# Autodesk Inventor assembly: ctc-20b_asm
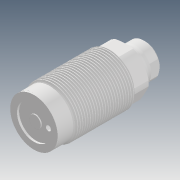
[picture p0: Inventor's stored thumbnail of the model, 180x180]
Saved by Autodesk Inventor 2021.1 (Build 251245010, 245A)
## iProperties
Created: 2018-08
Part Number: ctc-20b_asm
Description: STEP AP203
Document SubType Name: Assembly
Designer: user
Title: ctc-20b_asm.STEP
Revision Number: ÈÎºÎ
Sending System: SolidWorks 2015
Preprocessor: SwSTEP 2.0
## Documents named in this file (6)
- D:\Vault_2016\Projekty\Clamptek\Hydraulic\CTC\Inventor\ctc-20b\ctc-20b_asm.iam
- D:\Vault_2016\Projekty\Clamptek\Hydraulic\CTC\Inventor\ctc-20b\CTC-20BT.ipt
- D:\Vault_2016\Projekty\Clamptek\Hydraulic\CTC\Inventor\ctc-20b\CTC-20BHSG.ipt
- D:\Vault_2016\Projekty\Clamptek\Hydraulic\CTC\Inventor\ctc-20b\CTC-20HG.ipt
- D:\Vault_2016\Projekty\Clamptek\Hydraulic\CTC\Inventor\ctc-20b\CTC-20MD.ipt
- D:\Vault_2016\Projekty\Clamptek\Hydraulic\CTC\Inventor\ctc-20b\CTC-20DP.ipt
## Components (5 placed, 5 different names)
1. CTC-20BT_1
2. CTC-20BHSG_2
3. CTC-20HG_3
4. CTC-20MD_4
5. CTC-20DP_5
